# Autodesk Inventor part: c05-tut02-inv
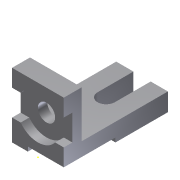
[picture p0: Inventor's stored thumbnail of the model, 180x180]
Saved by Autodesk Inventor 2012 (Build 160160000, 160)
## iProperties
Created: 2010-02
Part Number: c05-tut02-inv
Document SubType Name: Modeling
Designer: CADSoft
Density: 1 g/cm^3
Material: Default
Author: CADSoft
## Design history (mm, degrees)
sketch "Sketch1"
  geometry: 1 further point
sketch "Sketch2"
  geometry: L1 (0, 90)-(0, 0); L2 (0, 0)-(145, 0); L3 (145, 0)-(145, 25); L4 (145, 25)-(25, 25); L5 (25, 25)-(25, 90); L6 (25, 90)-(0, 90); 1 further point
  constraints: 12 end point, 1 coincident, 1 perpendicular, 1 other
  dimensions: "d0" = 90 distance of L1.start L1.end; "d1" = 25 distance of L5.end L1.start; "d2" = 145 distance of L1.end L2.end
extrude "Extrusion1" new body sketch "Sketch2" stored distance "d3" = 72; taper "d4" = 0 deg
sketch "Sketch3"
  geometry: L1 (0, 0)-(-6, -0.015); L2 (-6, -0.015)-(-6, 71.985); L3 (-6, 71.985)-(0, 72); L4 (0, 72)-(0, 0); L5 (0, 145)-(0, 0) reference
  constraints: 8 end point, 1 coincident, 1 point on line
  dimensions: "d5" = 72 distance of L3.end L1.start; "d6" = 6 distance of L1.start L1.end
extrude "Extrusion2" cut sketch "Sketch3" distance "d7" = 50; taper "d8" = 0 deg
sketch "Sketch4"
  geometry: L1 (72, -24)-(72, -60); L2 (0, -60)-(0, -24); L3 (0, -90)-(22, -90) reference; L4 (0, 0)-(0, -90) reference; L5 (72, -84)-(72, 0) reference; L6 (0, -24)-(12, -24); L7 (60, -24)-(72, -24); L8 (72, -60)-(60, -60); L9 (12, -60)-(0, -60); A1 r 30 centre (36, -42) between (12, -60) and (60, -60); A2 r 30 centre (36, -42) between (60, -24) and (12, -24)
  constraints: 12 end point, 4 point on circle, 2 centre point, 2 collinear, 1 concentric
  dimensions: "d10" = 48 distance from line of L3 A1.centre; "d11" = 36 distance from line of L4 A1.centre; "d14" = 30 radius of A2; "d15" = 36 distance of L2.start L2.end
extrude "Extrusion3" cut sketch "Sketch4" distance "d16" = 12; taper "d17" = 0 deg
sketch "Sketch5"
  geometry: C1 r 12 at (36, -42); A1 r 30 centre (36, -42) between (60, -24) and (12, -24) reference; 1 further point
  constraints: 1 centre point, 1 coincident
  dimensions: "d18" = 24 diameter of C1
extrude "Extrusion4" cut sketch "Sketch5" stored distance "d19" = 12; taper "d20" = 0 deg
sketch "Sketch6"
  geometry: L1 (24, 0)-(24, -50); L2 (48, -50)-(48, 0); L3 (48, 0)-(24, 0); L4 (72, 0)-(0, 0) reference; L5 (72, -120)-(72, 0) reference; A1 r 12 centre (36, -50) between (24, -50) and (48, -50); 1 further point
  constraints: 6 end point, 2 point on circle, 2 tangent, 2 vertical, 1 centre point, 1 collinear, 1 horizontal
  dimensions: "d21" = 50 distance of L2.start L2.end; "d22" = 12 radius of A1; "d23" = 36 distance from line of L5 A1.centre
extrude "Extrusion5" cut sketch "Sketch6" stored distance "d24" = 12; taper "d25" = 0 deg
body "Solid1"
